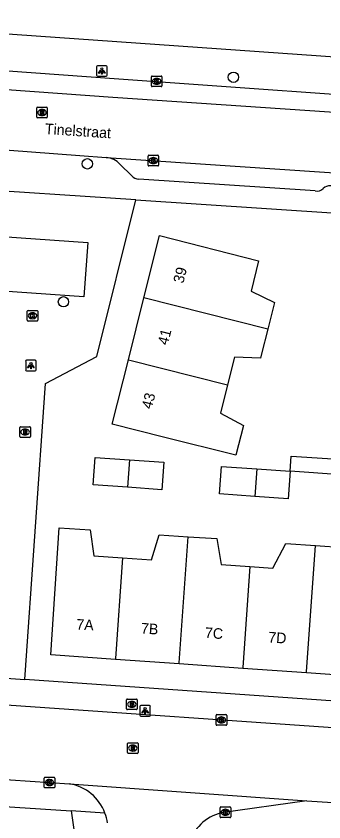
# Model space of a CAD drawing. Extents: x 159053 to 160041, y 380450 to 381422.
# Drawn here: x 159362.9 to 159391.9, y 381120.2 to 381196.2 of the extents above; entities that cross this region are included whole.
import ezdxf

# ---------------------------------------------------------------- set-up
doc = ezdxf.new("R2010")
doc.units = 0
for name, color, linetype in [('IMGEO_Boom', 7, 'Continuous'), ('IMGEO_Brandkraan', 7, 'Continuous'), ('IMGEO_Kolk', 7, 'Continuous'), ('IMGEO_Lichtpunt', 7, 'Continuous'), ('IMGEO_Openbare_ruimte_label', 7, 'Continuous'), ('IMGEO_Pand', 7, 'Continuous'), ('IMGEO_Pand_nummerreeks', 7, 'Continuous'), ('IMGEO_Rijbaan_lokaal_open', 7, 'Continuous'), ('IMGEO_Rioolput', 7, 'Continuous'), ('IMGEO_Voetpad_open', 7, 'Continuous')]:
    doc.layers.add(name, color=color, linetype=linetype)

msp = doc.modelspace()

# ---------------------------------------------------------------- linework, layer by layer
at = {"layer": 'IMGEO_Boom'}
for centre in [(159383.379, 381190.391), (159369.582, 381182.225), (159367.328, 381169.21)]:
    msp.add_circle(centre, 0.489, dxfattribs=at)
at = {"layer": 'IMGEO_Brandkraan'}
for p, q in [((159373.29, 381130.821), (159373.29, 381131.673)), ((159373.365, 381131.747), (159374.217, 381131.747)), ((159373.778, 381131.527), (159373.803, 381131.527)), ((159374.291, 381131.673), (159374.291, 381130.821)), ((159374.217, 381130.747), (159373.365, 381130.747)), ((159373.801, 381130.967), (159373.776, 381130.967))]:
    msp.add_line(p, q, dxfattribs=at)
for points in [[(159373.29, 381130.821), (159373.29, 381131.673)], [(159373.365, 381131.747), (159374.217, 381131.747)], [(159373.638, 381131.447), (159373.638, 381131.047), (159373.851, 381131.047)], [(159373.869, 381131.447), (159373.638, 381131.447)], [(159374.291, 381131.673), (159374.291, 381130.821)], [(159374.217, 381130.747), (159373.365, 381130.747)], [(159373.817, 381131.366), (159373.763, 381131.366), (159373.763, 381131.29)], [(159373.763, 381131.29), (159373.816, 381131.29)], [(159373.825, 381131.214), (159373.763, 381131.214), (159373.763, 381131.133)], [(159373.763, 381131.133), (159373.825, 381131.133)]]:
    msp.add_lwpolyline(points, dxfattribs=at)
for centre, radius, start, end in [((159373.367, 381131.671), 0.0765, 91.55205, 178.44795), ((159373.367, 381131.671), 0.0765, 91.55205, 178.44795), ((159373.873, 381131.302), 0.145, 59.4692, 91.53667), ((159373.898, 381131.349), 0.0922, 285.51372, 58.15012), ((159374.215, 381131.671), 0.0765, 1.55205, 88.44795), ((159374.215, 381131.671), 0.0765, 1.55205, 88.44795), ((159373.367, 381130.823), 0.0765, 181.55205, 268.44795), ((159373.367, 381130.823), 0.0765, 181.55205, 268.44795), ((159373.818, 381131.328), 0.0379, 267.82845, 90.93552), ((159373.826, 381131.173), 0.0404, 269.87594, 90.50774), ((159373.857, 381131.298), 0.251, 268.66757, 293.53466), ((159373.903, 381131.157), 0.105, 301.31148, 78.98903), ((159374.215, 381130.823), 0.0765, 271.55205, 358.44795), ((159374.215, 381130.823), 0.0765, 271.55205, 358.44795)]:
    msp.add_arc(centre, radius, start, end, dxfattribs=at)
for centre, major_axis, ratio, start_param, end_param in [((159373.777, 381131.247), (-0.387, 0.002), 0.722429, 4.712389, 7.853982), ((159373.802, 381131.247), (-0.39, 0.002), 0.717154, 1.570796, 4.712389)]:
    msp.add_ellipse(centre, major_axis=major_axis, ratio=ratio, start_param=start_param, end_param=end_param, dxfattribs=at)
at = {"layer": 'IMGEO_Kolk'}
for p, q in [((159375.634, 381189.579), (159375.634, 381190.431)), ((159375.709, 381190.505), (159376.561, 381190.505)), ((159376.122, 381190.285), (159376.147, 381190.285)), ((159376.635, 381190.431), (159376.635, 381189.579)), ((159376.561, 381189.505), (159375.709, 381189.505)), ((159376.145, 381189.725), (159376.12, 381189.725)), ((159375.316, 381182.1), (159375.316, 381182.952)), ((159375.391, 381183.026), (159376.243, 381183.026)), ((159375.804, 381182.806), (159375.829, 381182.806)), ((159376.317, 381182.952), (159376.317, 381182.1)), ((159376.243, 381182.026), (159375.391, 381182.026)), ((159375.827, 381182.246), (159375.802, 381182.246)), ((159363.906, 381167.466), (159363.906, 381168.318)), ((159363.981, 381168.392), (159364.833, 381168.392)), ((159364.394, 381168.172), (159364.419, 381168.172)), ((159364.907, 381168.318), (159364.907, 381167.466)), ((159364.833, 381167.392), (159363.981, 381167.392)), ((159364.417, 381167.612), (159364.392, 381167.612)), ((159381.746, 381129.347), (159381.746, 381130.199)), ((159381.821, 381130.273), (159382.673, 381130.273)), ((159382.234, 381130.053), (159382.259, 381130.053)), ((159382.747, 381130.199), (159382.747, 381129.347)), ((159382.673, 381129.273), (159381.821, 381129.273)), ((159382.257, 381129.493), (159382.232, 381129.493)), ((159365.506, 381123.444), (159365.506, 381124.296)), ((159365.581, 381124.37), (159366.433, 381124.37)), ((159365.994, 381124.15), (159366.019, 381124.15)), ((159366.507, 381124.296), (159366.507, 381123.444)), ((159366.433, 381123.37), (159365.581, 381123.37)), ((159366.017, 381123.59), (159365.992, 381123.59)), ((159382.199, 381121.563), (159383.051, 381121.563)), ((159382.124, 381120.637), (159382.124, 381121.489)), ((159382.635, 381120.783), (159382.61, 381120.783)), ((159382.612, 381121.343), (159382.637, 381121.343)), ((159383.125, 381121.489), (159383.125, 381120.637)), ((159383.051, 381120.563), (159382.199, 381120.563))]:
    msp.add_line(p, q, dxfattribs=at)
for points in [[(159375.634, 381189.579), (159375.634, 381190.431)], [(159375.709, 381190.505), (159376.561, 381190.505)], [(159375.955, 381190.205), (159376.078, 381190.205), (159376.078, 381190.054), (159376.208, 381190.205), (159376.372, 381190.205), (159376.226, 381190.054), (159376.379, 381189.805), (159376.227, 381189.805), (159376.142, 381189.969), (159376.078, 381189.902), (159376.078, 381189.805), (159375.955, 381189.805), (159375.955, 381190.205)], [(159376.635, 381190.431), (159376.635, 381189.579)], [(159376.561, 381189.505), (159375.709, 381189.505)], [(159375.316, 381182.1), (159375.316, 381182.952)], [(159375.391, 381183.026), (159376.243, 381183.026)], [(159375.637, 381182.726), (159375.76, 381182.726), (159375.76, 381182.575), (159375.89, 381182.726), (159376.054, 381182.726), (159375.908, 381182.575), (159376.061, 381182.326), (159375.909, 381182.326), (159375.824, 381182.49), (159375.76, 381182.423), (159375.76, 381182.326), (159375.637, 381182.326), (159375.637, 381182.726)], [(159376.317, 381182.952), (159376.317, 381182.1)], [(159376.243, 381182.026), (159375.391, 381182.026)], [(159363.906, 381167.466), (159363.906, 381168.318)], [(159363.981, 381168.392), (159364.833, 381168.392)], [(159364.227, 381168.092), (159364.35, 381168.092), (159364.35, 381167.941), (159364.48, 381168.092), (159364.644, 381168.092), (159364.498, 381167.941), (159364.651, 381167.692), (159364.499, 381167.692), (159364.414, 381167.856), (159364.35, 381167.789), (159364.35, 381167.692), (159364.227, 381167.692), (159364.227, 381168.092)], [(159364.907, 381168.318), (159364.907, 381167.466)], [(159364.833, 381167.392), (159363.981, 381167.392)], [(159381.746, 381129.347), (159381.746, 381130.199)], [(159381.821, 381130.273), (159382.673, 381130.273)], [(159382.067, 381129.973), (159382.19, 381129.973), (159382.19, 381129.822), (159382.32, 381129.973), (159382.484, 381129.973), (159382.338, 381129.822), (159382.491, 381129.573), (159382.339, 381129.573), (159382.254, 381129.737), (159382.19, 381129.67), (159382.19, 381129.573), (159382.067, 381129.573), (159382.067, 381129.973)], [(159382.747, 381130.199), (159382.747, 381129.347)], [(159382.673, 381129.273), (159381.821, 381129.273)], [(159365.506, 381123.444), (159365.506, 381124.296)], [(159365.581, 381124.37), (159366.433, 381124.37)], [(159365.827, 381124.07), (159365.95, 381124.07), (159365.95, 381123.919), (159366.08, 381124.07), (159366.244, 381124.07), (159366.098, 381123.919), (159366.251, 381123.67), (159366.099, 381123.67), (159366.014, 381123.834), (159365.95, 381123.767), (159365.95, 381123.67), (159365.827, 381123.67), (159365.827, 381124.07)], [(159366.507, 381124.296), (159366.507, 381123.444)], [(159366.433, 381123.37), (159365.581, 381123.37)], [(159382.199, 381121.563), (159383.051, 381121.563)], [(159382.124, 381120.637), (159382.124, 381121.489)], [(159382.445, 381121.263), (159382.568, 381121.263), (159382.568, 381121.112), (159382.698, 381121.263), (159382.862, 381121.263), (159382.716, 381121.112), (159382.869, 381120.863), (159382.717, 381120.863), (159382.632, 381121.027), (159382.568, 381120.96), (159382.568, 381120.863), (159382.445, 381120.863), (159382.445, 381121.263)], [(159383.125, 381121.489), (159383.125, 381120.637)], [(159383.051, 381120.563), (159382.199, 381120.563)]]:
    msp.add_lwpolyline(points, dxfattribs=at)
for centre, start, end in [((159375.711, 381190.429), 91.55205, 178.44795), ((159375.711, 381190.429), 91.55205, 178.44795), ((159376.559, 381190.429), 1.55205, 88.44795), ((159376.559, 381190.429), 1.55205, 88.44795), ((159375.711, 381189.581), 181.55205, 268.44795), ((159375.711, 381189.581), 181.55205, 268.44795), ((159376.559, 381189.581), 271.55205, 358.44795), ((159376.559, 381189.581), 271.55205, 358.44795), ((159375.393, 381182.95), 91.55205, 178.44795), ((159375.393, 381182.95), 91.55205, 178.44795), ((159376.241, 381182.95), 1.55205, 88.44795), ((159376.241, 381182.95), 1.55205, 88.44795), ((159375.393, 381182.102), 181.55205, 268.44795), ((159375.393, 381182.102), 181.55205, 268.44795), ((159376.241, 381182.102), 271.55205, 358.44795), ((159376.241, 381182.102), 271.55205, 358.44795), ((159363.983, 381168.316), 91.55205, 178.44795), ((159363.983, 381168.316), 91.55205, 178.44795), ((159364.831, 381168.316), 1.55205, 88.44795), ((159364.831, 381168.316), 1.55205, 88.44795), ((159363.983, 381167.468), 181.55205, 268.44795), ((159363.983, 381167.468), 181.55205, 268.44795), ((159364.831, 381167.468), 271.55205, 358.44795), ((159364.831, 381167.468), 271.55205, 358.44795), ((159381.823, 381130.197), 91.55205, 178.44795), ((159381.823, 381130.197), 91.55205, 178.44795), ((159382.671, 381130.197), 1.55205, 88.44795), ((159382.671, 381130.197), 1.55205, 88.44795), ((159381.823, 381129.349), 181.55205, 268.44795), ((159381.823, 381129.349), 181.55205, 268.44795), ((159382.671, 381129.349), 271.55205, 358.44795), ((159382.671, 381129.349), 271.55205, 358.44795), ((159365.583, 381124.294), 91.55205, 178.44795), ((159365.583, 381124.294), 91.55205, 178.44795), ((159366.431, 381124.294), 1.55205, 88.44795), ((159366.431, 381124.294), 1.55205, 88.44795), ((159365.583, 381123.446), 181.55205, 268.44795), ((159365.583, 381123.446), 181.55205, 268.44795), ((159366.431, 381123.446), 271.55205, 358.44795), ((159366.431, 381123.446), 271.55205, 358.44795), ((159382.201, 381121.487), 91.55205, 178.44795), ((159382.201, 381121.487), 91.55205, 178.44795), ((159383.049, 381121.487), 1.55205, 88.44795), ((159383.049, 381121.487), 1.55205, 88.44795), ((159382.201, 381120.639), 181.55205, 268.44795), ((159382.201, 381120.639), 181.55205, 268.44795), ((159383.049, 381120.639), 271.55205, 358.44795), ((159383.049, 381120.639), 271.55205, 358.44795)]:
    msp.add_arc(centre, 0.0765, start, end, dxfattribs=at)
for centre, major_axis, ratio, start_param, end_param in [((159376.121, 381190.005), (-0.387, 0.002), 0.722429, 4.712389, 7.853982), ((159376.146, 381190.005), (-0.39, 0.002), 0.717154, 1.570796, 4.712389), ((159375.803, 381182.526), (-0.387, 0.002), 0.722429, 4.712389, 7.853982), ((159375.828, 381182.526), (-0.39, 0.002), 0.717154, 1.570796, 4.712389), ((159364.393, 381167.892), (-0.387, 0.002), 0.722429, 4.712389, 7.853982), ((159364.418, 381167.892), (-0.39, 0.002), 0.717154, 1.570796, 4.712389), ((159382.233, 381129.773), (-0.387, 0.002), 0.722429, 4.712389, 7.853982), ((159382.258, 381129.773), (-0.39, 0.002), 0.717154, 1.570796, 4.712389), ((159365.993, 381123.87), (-0.387, 0.002), 0.722429, 4.712389, 7.853982), ((159366.018, 381123.87), (-0.39, 0.002), 0.717154, 1.570796, 4.712389), ((159382.611, 381121.063), (-0.387, 0.002), 0.722429, 4.712389, 7.853982), ((159382.636, 381121.063), (-0.39, 0.002), 0.717154, 1.570796, 4.712389)]:
    msp.add_ellipse(centre, major_axis=major_axis, ratio=ratio, start_param=start_param, end_param=end_param, dxfattribs=at)
at = {"layer": 'IMGEO_Lichtpunt'}
for p, q in [((159371.349, 381191.478), (159370.541, 381191.478)), ((159371.349, 381191.478), (159370.541, 381191.478)), ((159370.447, 381191.383), (159370.447, 381190.576)), ((159370.447, 381191.383), (159370.447, 381190.576)), ((159371.443, 381190.576), (159371.443, 381191.383)), ((159371.443, 381190.576), (159371.443, 381191.383)), ((159370.541, 381190.482), (159371.349, 381190.482)), ((159370.541, 381190.482), (159371.349, 381190.482)), ((159363.756, 381163.596), (159363.756, 381162.789)), ((159363.756, 381163.596), (159363.756, 381162.789)), ((159364.658, 381163.691), (159363.85, 381163.691)), ((159364.658, 381163.691), (159363.85, 381163.691)), ((159364.752, 381162.789), (159364.752, 381163.596)), ((159364.752, 381162.789), (159364.752, 381163.596)), ((159363.85, 381162.695), (159364.658, 381162.695)), ((159363.85, 381162.695), (159364.658, 381162.695)), ((159374.538, 381131.041), (159374.538, 381130.234)), ((159374.538, 381131.041), (159374.538, 381130.234)), ((159375.44, 381131.136), (159374.632, 381131.136)), ((159375.44, 381131.136), (159374.632, 381131.136)), ((159375.534, 381130.234), (159375.534, 381131.041)), ((159375.534, 381130.234), (159375.534, 381131.041)), ((159374.632, 381130.14), (159375.44, 381130.14)), ((159374.632, 381130.14), (159375.44, 381130.14))]:
    msp.add_line(p, q, dxfattribs=at)
for points in [[(159370.821, 381191.047), (159370.86, 381191.019), (159370.672, 381190.757), (159370.634, 381190.784), (159370.821, 381191.047)], [(159370.923, 381190.999), (159370.97, 381190.999), (159370.97, 381190.677), (159370.923, 381190.677), (159370.923, 381190.999)], [(159371.033, 381191.019), (159371.071, 381191.046), (159371.258, 381190.784), (159371.219, 381190.756), (159371.033, 381191.019)], [(159364.13, 381163.26), (159364.169, 381163.232), (159363.981, 381162.97), (159363.943, 381162.997), (159364.13, 381163.26)], [(159364.232, 381163.212), (159364.279, 381163.212), (159364.279, 381162.89), (159364.232, 381162.89), (159364.232, 381163.212)], [(159364.342, 381163.232), (159364.38, 381163.259), (159364.567, 381162.997), (159364.528, 381162.969), (159364.342, 381163.232)], [(159374.912, 381130.705), (159374.951, 381130.677), (159374.763, 381130.415), (159374.725, 381130.442), (159374.912, 381130.705)], [(159375.124, 381130.677), (159375.162, 381130.704), (159375.349, 381130.442), (159375.31, 381130.414), (159375.124, 381130.677)], [(159375.014, 381130.657), (159375.061, 381130.657), (159375.061, 381130.335), (159375.014, 381130.335), (159375.014, 381130.657)]]:
    msp.add_lwpolyline(points, dxfattribs=at)
for centre in [(159370.946, 381191.181), (159364.255, 381163.394), (159375.037, 381130.839)]:
    msp.add_circle(centre, 0.0994, dxfattribs=at)
for centre, start, end in [((159370.541, 381191.383), 90, 180), ((159370.541, 381191.383), 90, 180), ((159371.349, 381191.383), 0, 90), ((159371.349, 381191.383), 0, 90), ((159370.541, 381190.576), 180, 270), ((159370.541, 381190.576), 180, 270), ((159371.349, 381190.576), 270, 0), ((159371.349, 381190.576), 270, 360), ((159363.85, 381163.596), 90, 180), ((159363.85, 381163.596), 90, 180), ((159364.658, 381163.596), 0, 90), ((159364.658, 381163.596), 0, 90), ((159363.85, 381162.789), 180, 270), ((159363.85, 381162.789), 180, 270), ((159364.658, 381162.789), 270, 0), ((159364.658, 381162.789), 270, 360), ((159374.632, 381131.041), 90, 180), ((159374.632, 381131.041), 90, 180), ((159375.44, 381131.041), 0, 90), ((159375.44, 381131.041), 0, 90), ((159374.632, 381130.234), 180, 270), ((159374.632, 381130.234), 180, 270), ((159375.44, 381130.234), 270, 0), ((159375.44, 381130.234), 270, 360)]:
    msp.add_arc(centre, 0.0946, start, end, dxfattribs=at)
at = {"layer": 'IMGEO_Pand'}
for points in [[(159374.933, 381169.581), (159376.412, 381175.454), (159385.757, 381173.074), (159385.047, 381170.213), (159387.253, 381169.152), (159386.62, 381166.638)], [(159373.461, 381163.737), (159374.933, 381169.581)], [(159386.62, 381166.638), (159374.933, 381169.581)], [(159386.62, 381166.638), (159386.032, 381164.304), (159385.928, 381163.89), (159383.482, 381164), (159382.822, 381161.38)], [(159382.822, 381161.38), (159382.15, 381158.709), (159384.327, 381157.532), (159383.622, 381154.731), (159376.783, 381156.453), (159371.934, 381157.674), (159373.461, 381163.737)], [(159373.461, 381163.737), (159382.822, 381161.38)], [(159373.377, 381151.717), (159370.146, 381151.948), (159370.331, 381154.54), (159373.559, 381154.309)], [(159373.559, 381154.309), (159376.811, 381154.077), (159376.626, 381151.485), (159373.377, 381151.717)], [(159373.559, 381154.309), (159373.377, 381151.717)], [(159385.404, 381150.857), (159382.079, 381151.095), (159382.265, 381153.687), (159385.586, 381153.45)], [(159385.586, 381153.45), (159385.404, 381150.857)], [(159388.745, 381153.224), (159388.56, 381150.631), (159385.404, 381150.857)], [(159385.586, 381153.45), (159388.745, 381153.224)], [(159372.237, 381135.473), (159366.145, 381135.9), (159366.932, 381147.897), (159369.838, 381147.697), (159370.202, 381145.264), (159372.911, 381145.077)], [(159372.911, 381145.077), (159375.654, 381144.888), (159376.378, 381147.246), (159379.094, 381147.059)], [(159378.252, 381135.051), (159378.259, 381135.155), (159379.094, 381147.059)], [(159379.094, 381147.059), (159381.83, 381146.871), (159382.214, 381144.436), (159384.941, 381144.249)], [(159384.941, 381144.249), (159387.117, 381144.099), (159388.35, 381146.421), (159391.124, 381146.23)], [(159391.124, 381146.23), (159393.812, 381146.045), (159394.136, 381143.615), (159397.102, 381143.411), (159396.782, 381138.764), (159396.438, 381133.775), (159390.28, 381134.207)], [(159390.28, 381134.207), (159390.287, 381134.311), (159391.124, 381146.23)], [(159372.911, 381145.077), (159372.244, 381135.577), (159372.237, 381135.473)], [(159384.941, 381144.249), (159384.273, 381134.733), (159384.266, 381134.629)], [(159378.252, 381135.051), (159372.237, 381135.473)], [(159384.266, 381134.629), (159378.252, 381135.051)], [(159390.28, 381134.207), (159384.266, 381134.629)]]:
    msp.add_lwpolyline(points, dxfattribs=at)
at = {"layer": 'IMGEO_Rijbaan_lokaal_open'}
for points in [[(159410.545, 381185.773), (159398.502, 381186.692), (159371.994, 381188.49), (159359.323, 381189.387), (159340.654, 381190.693), (159337.916, 381190.875)], [(159355.92, 381183.977), (159359.695, 381183.717), (159368.882, 381183.022), (159371.374, 381182.825)], [(159371.374, 381182.825), (159487.158, 381175.068), (159489.604, 381174.872)], [(159408.675, 381127.944), (159347.843, 381132.155)], [(159347.425, 381125.142), (159367.896, 381123.741)], [(159367.896, 381123.741), (159390.325, 381122.15)], [(159390.325, 381122.15), (159382.229, 381121.007)], [(159390.325, 381122.15), (159408.288, 381120.979)]]:
    msp.add_lwpolyline(points, dxfattribs=at)
for centre, radius, start, end in [((159367.212, 381119.488), 4.308, 20.3669, 80.8704), ((159367.251, 381119.5), 4.267, 7.68473, 20.38776), ((159383.195, 381117.006), 4.116, 103.57512, 165.64198)]:
    msp.add_arc(centre, radius, start, end, dxfattribs=at)
at = {"layer": 'IMGEO_Rioolput'}
for p, q in [((159364.801, 381186.639), (159364.801, 381187.491)), ((159364.876, 381187.565), (159365.728, 381187.565)), ((159365.289, 381187.345), (159365.314, 381187.345)), ((159365.802, 381187.491), (159365.802, 381186.639)), ((159365.728, 381186.565), (159364.876, 381186.565)), ((159365.312, 381186.785), (159365.287, 381186.785)), ((159363.201, 381156.502), (159363.201, 381157.354)), ((159363.276, 381157.428), (159364.128, 381157.428)), ((159364.202, 381157.354), (159364.202, 381156.502)), ((159363.712, 381156.648), (159363.687, 381156.648)), ((159363.689, 381157.208), (159363.714, 381157.208)), ((159364.128, 381156.428), (159363.276, 381156.428)), ((159373.376, 381126.691), (159373.376, 381127.543)), ((159373.451, 381127.617), (159374.303, 381127.617)), ((159373.864, 381127.397), (159373.889, 381127.397)), ((159374.377, 381127.543), (159374.377, 381126.691)), ((159374.303, 381126.617), (159373.451, 381126.617)), ((159373.887, 381126.837), (159373.862, 381126.837))]:
    msp.add_line(p, q, dxfattribs=at)
for points in [[(159364.801, 381186.639), (159364.801, 381187.491)], [(159364.876, 381187.565), (159365.728, 381187.565)], [(159365.39, 381187.263), (159365.138, 381187.265), (159365.138, 381186.865)], [(159365.138, 381186.865), (159365.262, 381186.865), (159365.262, 381187.027), (159365.273, 381187.027)], [(159365.316, 381187.184), (159365.262, 381187.184), (159365.262, 381187.103)], [(159365.262, 381187.103), (159365.314, 381187.103)], [(159365.32, 381186.998), (159365.391, 381186.865), (159365.531, 381186.865), (159365.466, 381186.991)], [(159365.802, 381187.491), (159365.802, 381186.639)], [(159365.728, 381186.565), (159364.876, 381186.565)], [(159363.201, 381156.502), (159363.201, 381157.354)], [(159363.276, 381157.428), (159364.128, 381157.428)], [(159364.202, 381157.354), (159364.202, 381156.502)], [(159363.79, 381157.126), (159363.538, 381157.128), (159363.538, 381156.728)], [(159363.538, 381156.728), (159363.662, 381156.728), (159363.662, 381156.89), (159363.673, 381156.89)], [(159363.716, 381157.047), (159363.662, 381157.047), (159363.662, 381156.966)], [(159363.662, 381156.966), (159363.714, 381156.966)], [(159363.72, 381156.861), (159363.791, 381156.728), (159363.931, 381156.728), (159363.866, 381156.854)], [(159364.128, 381156.428), (159363.276, 381156.428)], [(159373.376, 381126.691), (159373.376, 381127.543)], [(159373.451, 381127.617), (159374.303, 381127.617)], [(159373.965, 381127.315), (159373.713, 381127.317), (159373.713, 381126.917)], [(159373.713, 381126.917), (159373.837, 381126.917), (159373.837, 381127.079), (159373.848, 381127.079)], [(159373.891, 381127.236), (159373.837, 381127.236), (159373.837, 381127.155)], [(159373.837, 381127.155), (159373.889, 381127.155)], [(159373.895, 381127.05), (159373.966, 381126.917), (159374.106, 381126.917), (159374.041, 381127.043)], [(159374.377, 381127.543), (159374.377, 381126.691)], [(159374.303, 381126.617), (159373.451, 381126.617)]]:
    msp.add_lwpolyline(points, dxfattribs=at)
for centre, radius, start, end in [((159364.878, 381187.489), 0.0765, 91.55205, 178.44795), ((159364.878, 381187.489), 0.0765, 91.55205, 178.44795), ((159365.272, 381186.974), 0.0533, 26.02933, 88.69889), ((159365.298, 381187.292), 0.19, 274.7715, 282.96867), ((159365.322, 381187.088), 0.0964, 77.00612, 93.18647), ((159365.336, 381187.145), 0.0378, 276.66336, 79.67722), ((159365.389, 381187.153), 0.109, 350.36119, 89.41601), ((159365.387, 381187.153), 0.112, 277.58423, 350.98172), ((159365.371, 381186.938), 0.108, 29.51342, 73.79051), ((159365.726, 381187.489), 0.0765, 1.55205, 88.44795), ((159365.726, 381187.489), 0.0765, 1.55205, 88.44795), ((159364.878, 381186.641), 0.0765, 181.55205, 268.44795), ((159364.878, 381186.641), 0.0765, 181.55205, 268.44795), ((159365.726, 381186.641), 0.0765, 271.55205, 358.44795), ((159365.726, 381186.641), 0.0765, 271.55205, 358.44795), ((159363.278, 381157.352), 0.0765, 91.55205, 178.44795), ((159363.278, 381157.352), 0.0765, 91.55205, 178.44795), ((159364.126, 381157.352), 0.0765, 1.55205, 88.44795), ((159364.126, 381157.352), 0.0765, 1.55205, 88.44795), ((159363.278, 381156.504), 0.0765, 181.55205, 268.44795), ((159363.278, 381156.504), 0.0765, 181.55205, 268.44795), ((159363.672, 381156.837), 0.0533, 26.02933, 88.69889), ((159363.698, 381157.155), 0.19, 274.7715, 282.96867), ((159363.722, 381156.951), 0.0964, 77.00612, 93.18647), ((159363.736, 381157.008), 0.0378, 276.66336, 79.67722), ((159363.789, 381157.016), 0.109, 350.36119, 89.41601), ((159363.787, 381157.016), 0.112, 277.58423, 350.98172), ((159363.771, 381156.801), 0.108, 29.51342, 73.79051), ((159364.126, 381156.504), 0.0765, 271.55205, 358.44795), ((159364.126, 381156.504), 0.0765, 271.55205, 358.44795), ((159373.453, 381127.541), 0.0765, 91.55205, 178.44795), ((159373.453, 381127.541), 0.0765, 91.55205, 178.44795), ((159373.847, 381127.026), 0.0533, 26.02933, 88.69889), ((159373.873, 381127.344), 0.19, 274.7715, 282.96867), ((159373.897, 381127.14), 0.0964, 77.00612, 93.18647), ((159373.911, 381127.197), 0.0378, 276.66336, 79.67722), ((159373.964, 381127.205), 0.109, 350.36119, 89.41601), ((159373.962, 381127.205), 0.112, 277.58423, 350.98172), ((159373.946, 381126.99), 0.108, 29.51342, 73.79051), ((159374.301, 381127.541), 0.0765, 1.55205, 88.44795), ((159374.301, 381127.541), 0.0765, 1.55205, 88.44795), ((159373.453, 381126.693), 0.0765, 181.55205, 268.44795), ((159373.453, 381126.693), 0.0765, 181.55205, 268.44795), ((159374.301, 381126.693), 0.0765, 271.55205, 358.44795), ((159374.301, 381126.693), 0.0765, 271.55205, 358.44795)]:
    msp.add_arc(centre, radius, start, end, dxfattribs=at)
for centre, major_axis, ratio, start_param, end_param in [((159365.288, 381187.065), (-0.387, 0.002), 0.722429, 4.712389, 7.853982), ((159365.313, 381187.065), (-0.39, 0.002), 0.717154, 1.570796, 4.712389), ((159363.688, 381156.928), (-0.387, 0.002), 0.722429, 4.712389, 7.853982), ((159363.713, 381156.928), (-0.39, 0.002), 0.717154, 1.570796, 4.712389), ((159373.863, 381127.117), (-0.387, 0.002), 0.722429, 4.712389, 7.853982), ((159373.888, 381127.117), (-0.39, 0.002), 0.717154, 1.570796, 4.712389)]:
    msp.add_ellipse(centre, major_axis=major_axis, ratio=ratio, start_param=start_param, end_param=end_param, dxfattribs=at)
at = {"layer": 'IMGEO_Voetpad_open'}
for points in [[(159412.725, 381190.897), (159337.817, 381196.156)], [(159338.035, 381192.671), (159340.776, 381192.489), (159359.449, 381191.183), (159372.118, 381190.286), (159404.772, 381187.938), (159407.806, 381187.721)], [(159373.771, 381181.088), (159372.664, 381182.192)], [(159391.104, 381179.669), (159374.453, 381180.793)], [(159374.158, 381178.842), (159356.901, 381179.946), (159356.805, 381178.73)], [(159363.677, 381133.592), (159365.639, 381161.495), (159370.465, 381164.045), (159374.158, 381178.842)], [(159374.158, 381178.842), (159399.325, 381177.147)], [(159359.337, 381170.372), (159359.717, 381175.487), (159369.64, 381174.79), (159369.266, 381169.669), (159359.337, 381170.372)], [(159388.745, 381153.224), (159388.848, 381154.667), (159395.186, 381154.243)], [(159393.57, 381152.879), (159388.745, 381153.224)], [(159360.526, 381133.81), (159363.677, 381133.592)], [(159398.457, 381131.162), (159363.677, 381133.592)], [(159359.798, 381121.745), (159368.043, 381121.201)], [(159371.251, 381120.987), (159368.043, 381121.201)], [(159368.043, 381121.201), (159372.107, 381092.995)]]:
    msp.add_lwpolyline(points, dxfattribs=at)
for centre, radius, start, end in [((159371.18, 381180.799), 2.035, 43.19081, 84.53503), ((159374.444, 381181.708), 0.915, 222.64534, 270.57274), ((159392.508, 381179.161), 0.992, 40.76777, 131.43124), ((159391.26, 381180.475), 0.821, 259.03414, 316.03168)]:
    msp.add_arc(centre, radius, start, end, dxfattribs=at)

# ---------------------------------------------------------------- texts
at = {"layer": 'IMGEO_Openbare_ruimte_label'}
msp.add_text('Tinelstraat', height=1, rotation=356.15925, dxfattribs=at).set_placement((159365.55, 381185.044))
at = {"layer": 'IMGEO_Pand_nummerreeks'}
for s, rotation, p in [('39', 75.86371, (159378.645, 381170.888)), ('41', 75.86371, (159377.179, 381165.071)), ('43', 75.86371, (159375.66, 381159.035)), ('7A', 356.96847, (159368.525, 381138.298)), ('7B', 355.98682, (159374.625, 381137.936)), ('7C', 355.98616, (159380.665, 381137.513)), ('7D', 355.98616, (159386.654, 381137.092))]:
    msp.add_text(s, height=1, rotation=rotation, dxfattribs=at).set_placement(p)

doc.saveas('drawing.dxf')
